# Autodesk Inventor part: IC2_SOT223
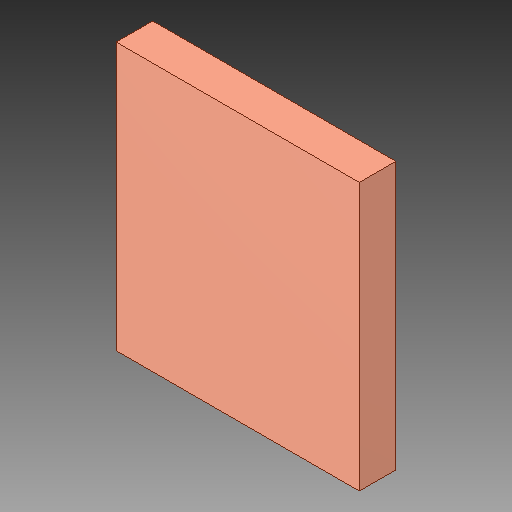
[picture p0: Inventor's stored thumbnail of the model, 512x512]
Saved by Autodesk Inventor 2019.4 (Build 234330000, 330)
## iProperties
Created: 2019-11
Part Number: IC2_SOT223
Material: Generic
Document SubType Name: Modeling
Designer: Willist
Density: 1 g/cm^3
Appearance: SOT223, IC2_SOT223
Author: Willist
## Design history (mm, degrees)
sketch "SOT223, IC2_SOT223_33"
  geometry: L1 (-3.277, 3.658)-(3.378, 3.658); L2 (3.378, 3.658)-(3.378, -3.658); L3 (3.378, -3.658)-(-3.277, -3.658); L4 (-3.277, -3.658)-(-3.277, 3.658)
  constraints: 8 end point
extrude "Extrusion1" join sketch "SOT223, IC2_SOT223_33" distance "d0" = 1; taper "d1" = 0 deg
body "Solid1"
